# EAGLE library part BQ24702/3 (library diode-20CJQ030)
TI's BQ24702/3 Multichemistry Batter Charger Controller ans System Poer Selector DESCRIPTION: The bq24702/bq24703 is a highly integrated battery charge controller and selector tailored for notebook and sub-notebook PC applications. The bq24702/bq24703 uses dynamic power management (DPM) to minimize battery charge time by maximizing use of available wall-adapter power. This is achieved by dynamically adjusting the battery charge current based on the total system (adapter) current. The bq24702/bq24703 uses a fixed frequency, pulse width modulator (PWM) to accurately control battery charge current and voltage. Charge current limits can be programmed from a keyboard controller DAC or by external resistor dividers from the precision 5-V, ±0.6%, externally bypassed voltage reference (VREF), supplied by the bq24702/bq24703. FEATURES: Dynamic Power Management, DPM Minimizes Battery Charge Time Integrated Selector Supports Battery Conditioning and Smart Battery Learn Cycle Zero Volt Operation Selector Feedback Circuit Ensures Break-Before-Make Transition ±0.4% Charge Voltage Accuracy, Suitable for Charging Li-Ion Cells ±4% Charge Current Accuracy 300-kHz Integrated PWM Controller for High-Efficiency Buck Regulation Depleted Battery Detection and Indication to Protect Battery From Over Discharge 20-uA Sleep Mode Current for Low Battery Drain 24-Pin TSSOP Package and 5 mm × 5 mm QFN package (bq24703 only) Please send any comments to: messi@users.sourceforge.net
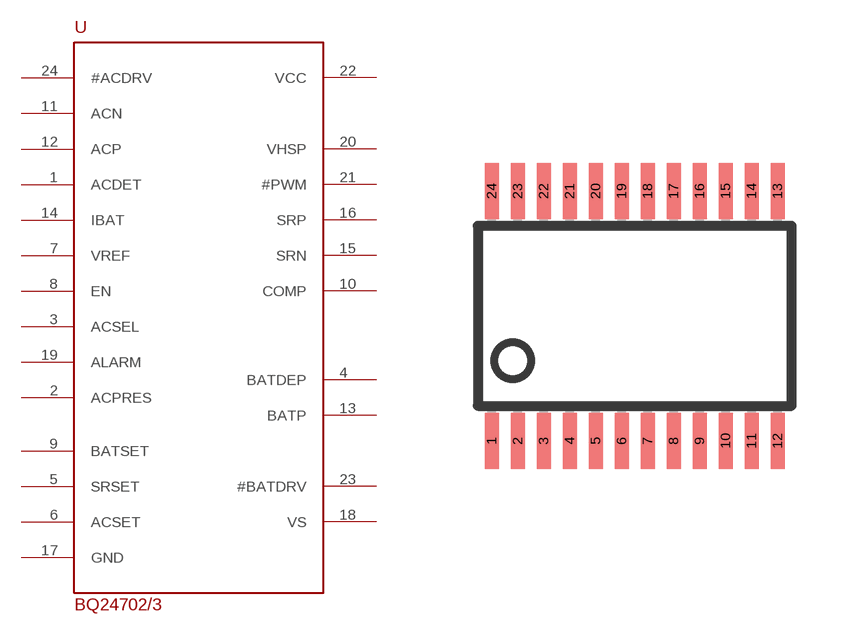
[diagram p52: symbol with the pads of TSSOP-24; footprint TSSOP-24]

Designator prefix U

## BQ24702/3  [TSSOP-24]
1  ACDET  in
2  ACPRES  out
3  ACSEL  in
4  BATDEP  in
5  SRSET  in
6  ACSET  in
7  VREF  out
8  EN  in
9  BATSET  in
10  COMP  out
11  ACN  in
12  ACP  in
13  BATP  in
14  IBAT  out
15  SRN  in
16  SRP  in
17  GND  pwr
18  VS  in
19  ALARM  out
20  VHSP  out
21  #PWM  out
22  VCC  pwr
23  #BATDRV  out
24  #ACDRV  out

## Footprint TSSOP-24 (pad centres in mm)
TSSOP-24 4.5mm body ie. bq24702/3
smd 0.35 x 1.4: 1 -3.725,-3.125; 2 -3.075,-3.125; 3 -2.425,-3.125; 4 -1.775,-3.125; 5 -1.125,-3.125; 6 -0.475,-3.125; 7 0.175,-3.125; 8 0.825,-3.125; 9 1.475,-3.125; 10 2.125,-3.125; 11 2.775,-3.125; 12 3.425,-3.125; 13 3.425,3.125; 14 2.775,3.125; 15 2.125,3.125; 16 1.475,3.125; 17 0.825,3.125; 18 0.175,3.125; 19 -0.475,3.125; 20 -1.125,3.125; 21 -1.775,3.125; 22 -2.425,3.125; 23 -3.075,3.125; 24 -3.725,3.125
